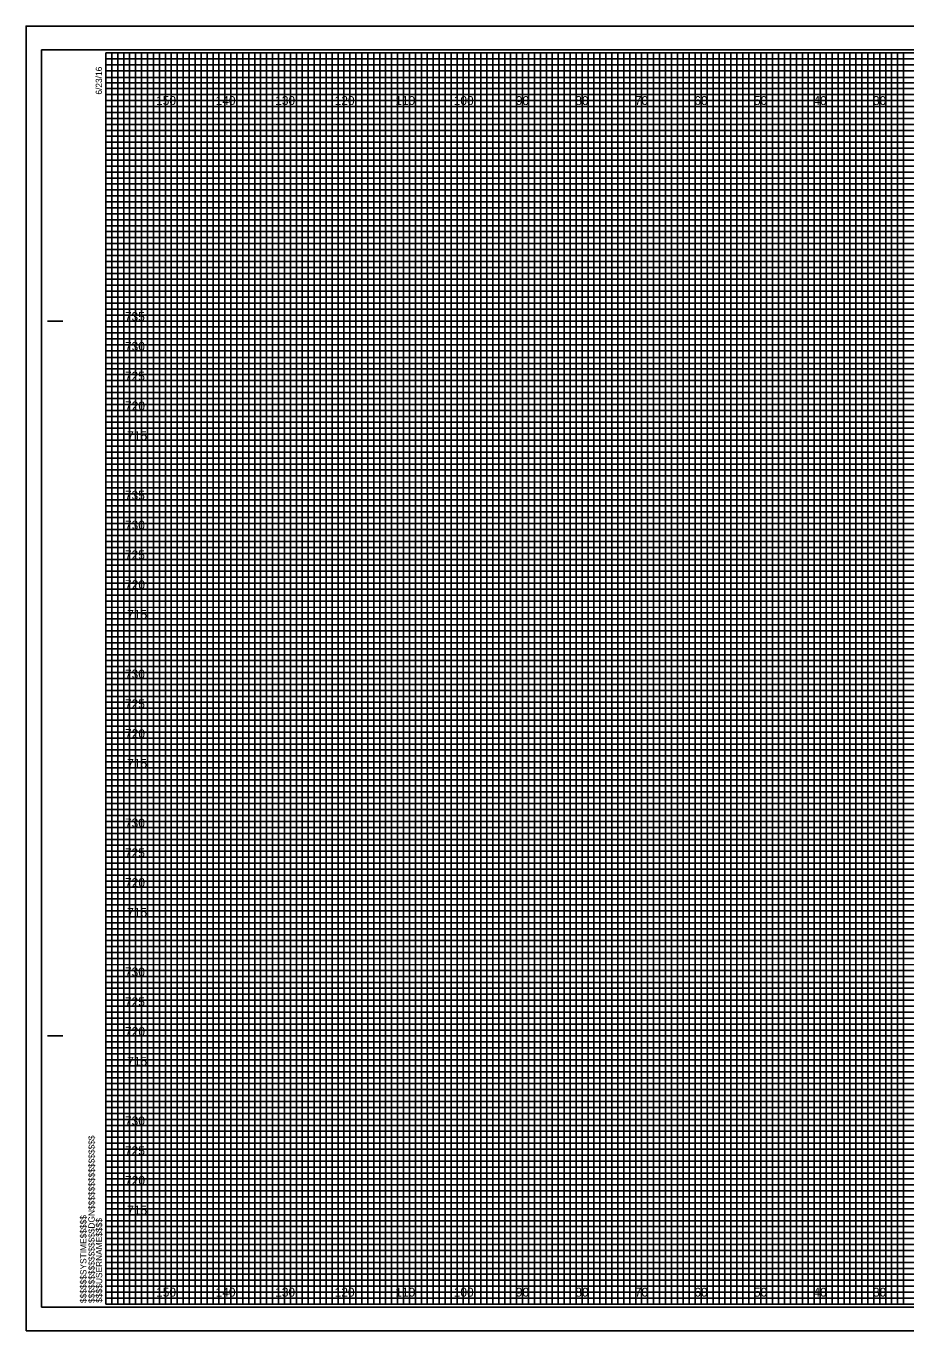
# Model space of a CAD drawing. Extents: x -13 to 323, y -5 to 434.
# Drawn here: x -13.4 to 134.4, y -4.5 to 214.5 of the extents above; entities that cross this region are included whole.
import ezdxf

# ---------------------------------------------------------------- set-up
doc = ezdxf.new("R2010")
doc.units = 0
for name, color, linetype in [('Prop XS Elevation Labels', 7, 'Continuous'), ('Prop XS Offset Labels', 7, 'Continuous'), ('Sheet Cross Section CELL', 7, 'Continuous'), ('Sheet Cross Section Grid Major CELL', 7, 'Continuous'), ('Sheet Cross Section Grid Middle CELL', 7, 'Continuous'), ('Sheet Cross Section Grid Minor 1 CELL', 7, 'Continuous'), ('Sheet Cross Section Grid Minor 2 CELL', 7, 'Continuous'), ('Sheet Cutting Line CELL', 7, 'Continuous'), ('Sheet DOT Grid CELL', 7, 'Continuous'), ('Sheet Plot Border Inside CELL', 7, 'Continuous'), ('Sheet Plot Border Outside CELL', 7, 'Continuous')]:
    doc.layers.add(name, color=color, linetype=linetype)

msp = doc.modelspace()

# ---------------------------------------------------------------- linework, layer by layer
at = {"layer": 'Sheet Cross Section CELL'}
for p, q in [((-9.8, 165), (-7.3, 165)), ((-9.7, 165), (-7.2, 165)), ((-9.8, 45), (-7.3, 45)), ((-9.7, 45), (-7.2, 45)), ((0, 0), (0, 0)), ((0, 0), (0, 0)), ((0, 0), (0, 0)), ((0, 0), (0, 0)), ((0, 0), (0, 0)), ((0, 0), (0, 0)), ((0, 0), (0, 0))]:
    msp.add_line(p, q, dxfattribs=at)
msp.add_lwpolyline([(320, 210), (0, 210), (0, 0), (320, 0)], close=True, dxfattribs=at)
at = {"layer": 'Sheet Cross Section Grid Major CELL'}
for p, q in [((10, 210), (0, 210)), ((10, 0), (10, 210)), ((30, 210), (20, 210)), ((20, 210), (20, 0)), ((30, 0), (30, 210)), ((50, 210), (40, 210)), ((40, 210), (40, 0)), ((50, 0), (50, 210)), ((70, 210), (60, 210)), ((60, 210), (60, 0)), ((70, 0), (70, 210)), ((90, 210), (80, 210)), ((80, 210), (80, 0)), ((90, 0), (90, 210)), ((110, 210), (100, 210)), ((100, 210), (100, 0)), ((110, 0), (110, 210)), ((130, 210), (120, 210)), ((120, 210), (120, 0)), ((130, 0), (130, 210)), ((20, 0), (10, 0)), ((40, 0), (30, 0)), ((60, 0), (50, 0)), ((80, 0), (70, 0)), ((100, 0), (90, 0)), ((120, 0), (110, 0)), ((140, 0), (130, 0))]:
    msp.add_line(p, q, dxfattribs=at)
for points in [[(0, 200), (320, 200), (320, 190), (0, 190)], [(0, 180), (320, 180), (320, 170), (0, 170)], [(0, 160), (320, 160), (320, 150), (0, 150)], [(0, 140), (320, 140), (320, 130), (0, 130)], [(0, 120), (320, 120), (320, 110), (0, 110)], [(0, 100), (320, 100), (320, 90), (0, 90)], [(0, 80), (320, 80), (320, 70), (0, 70)], [(0, 60), (320, 60), (320, 50), (0, 50)], [(0, 40), (320, 40), (320, 30), (0, 30)], [(0, 20), (320, 20), (320, 10), (0, 10)]]:
    msp.add_lwpolyline(points, dxfattribs=at)
at = {"layer": 'Sheet Cross Section Grid Middle CELL'}
for points in [[(0, 210), (5, 210), (5, 0), (15, 0), (15, 210), (25, 210), (25, 0), (35, 0), (35, 210), (45, 210), (45, 0), (55, 0), (55, 210), (65, 210), (65, 0), (75, 0), (75, 210), (85, 210), (85, 0), (95, 0), (95, 210), (105, 210), (105, 0), (115, 0), (115, 210), (125, 210), (125, 0), (135, 0)], [(0, 205), (275, 205)], [(0, 185), (320, 185), (320, 195), (0, 195)], [(0, 165), (320, 165), (320, 175), (0, 175)], [(0, 145), (320, 145), (320, 155), (0, 155)], [(0, 125), (320, 125), (320, 135), (0, 135)], [(0, 105), (320, 105), (320, 115), (0, 115)], [(0, 85), (320, 85), (320, 95), (0, 95)], [(0, 65), (320, 65), (320, 75), (0, 75)], [(0, 45), (320, 45), (320, 55), (0, 55)], [(0, 25), (320, 25), (320, 35), (0, 35)], [(0, 5), (320, 5), (320, 15), (0, 15)]]:
    msp.add_lwpolyline(points, dxfattribs=at)
at = {"layer": 'Sheet Cross Section Grid Minor 1 CELL'}
for p, q in [((0, 209), (260, 209)), ((260, 207.98), (0, 207.98)), ((0, 207.98), (0, 207)), ((0, 207), (260, 207)), ((260, 205.89), (0, 205.89)), ((0, 205.89), (0, 204)), ((0, 204), (320, 204))]:
    msp.add_line(p, q, dxfattribs=at)
for points in [[(0, 203), (270, 203), (320, 203), (320, 202), (0, 202)], [(0, 201), (320, 201), (320, 199), (0, 199)], [(0, 198), (320, 198), (320, 197), (0, 196.98)], [(0, 196), (320, 196), (320, 194), (0, 194)], [(0, 193), (320, 193), (320, 192), (0, 192)], [(0, 191), (320, 191), (320, 189), (0, 189)], [(0, 188), (320, 188), (320, 187), (0, 187)], [(0, 186), (320, 186), (320, 184), (0, 184)], [(0, 183), (320, 183), (320, 182), (0, 182)], [(0, 181), (320, 181), (320, 179), (0, 179)], [(0, 178), (320, 178), (320, 177), (0, 177)], [(0, 176), (320, 176), (320, 173.95), (320, 173), (320, 172), (0, 172)], [(0, 174), (320, 174), (320, 173), (0, 173)], [(0, 171), (320, 171), (320, 169), (0, 169.03)], [(0, 169.03), (320, 169), (320, 168), (0, 168)], [(0, 167), (320, 167), (320, 166), (0, 166)], [(0, 164), (320, 164), (320, 163), (0, 163)], [(0, 162), (320, 162), (320, 161), (0, 161)], [(-0.07, 158.89), (320, 158.89), (320, 157.88), (-0.07, 157.88)], [(0, 157), (320, 157), (320, 156), (0, 156)], [(0, 154), (320, 154), (320, 153), (0, 153)], [(0, 152), (320, 152), (320, 151), (0, 151)], [(0, 149), (320, 149), (320, 148), (0, 148)], [(0, 147), (320, 147), (320, 146), (0, 146)], [(0, 144), (320, 144), (320, 143), (0, 143)], [(0, 142), (320, 142), (320, 141), (0, 141)], [(0, 139), (320, 139), (319.99, 137.98), (0, 138)], [(0, 137), (320, 137), (320, 136), (0, 136)], [(0, 134), (320, 134), (320, 133), (0, 133)], [(0, 132), (320, 132), (320, 131), (0, 131)], [(0, 129), (320, 129), (320, 128), (0, 128)], [(0, 127), (320, 127), (320, 126), (0, 126)], [(0, 124), (320, 124), (320, 123), (0, 123)], [(0, 122), (320, 122), (320, 121), (0, 121)], [(0, 119), (320, 119), (320, 118), (0, 118)], [(0, 116.99), (320.07, 116.91), (320, 116), (0, 116)], [(0, 114), (320, 114), (320, 113), (0, 113)], [(0, 112), (320, 112), (320, 111), (0, 111)], [(0, 109), (320, 109), (320, 108), (0, 108)], [(0, 107), (320, 107), (320, 106), (0, 106)], [(0, 104), (320, 104), (320, 103), (0, 103)], [(0, 102), (320, 102), (320, 101), (0, 101)], [(0, 99), (320, 99), (320, 98), (0, 98)], [(0, 97), (320, 97), (320, 96), (0, 96)], [(0, 94), (320, 94), (320, 93), (0, 93)], [(0, 92), (320, 92), (320, 91), (0, 91)], [(0, 89), (320, 89), (320, 88), (0, 88)], [(0, 87), (320, 87), (320, 86), (0, 86)], [(0, 84), (320, 84), (320, 83), (0, 83)], [(0, 82), (320, 82), (320, 81), (0, 81)], [(0, 79), (320, 79), (319.99, 77.98), (0, 78)], [(0, 77), (320, 77), (320, 76), (0, 76)], [(0, 74), (320, 74), (320, 73), (0, 73)], [(0, 72), (320, 72), (320, 71), (0, 71)], [(0, 69), (320, 69), (320, 68), (0, 68)], [(0, 67), (320, 67), (320, 66), (0, 66)], [(0, 64), (320, 64), (320, 63), (0, 63)], [(0, 62), (320, 62), (320, 61), (0, 61)], [(0, 59), (320, 59), (320, 58), (0, 58)], [(0, 56.99), (320.07, 56.91), (320, 56), (0, 56)], [(0, 54), (320, 54), (320, 53), (0, 53)], [(0, 52), (320, 52), (320, 51), (0, 51)], [(0, 49), (320, 49), (320, 48), (0, 48)], [(0, 47), (320, 47), (320, 46), (0, 46)], [(0, 44), (320, 44), (320, 43), (0, 43)], [(0, 42), (320, 42), (320, 41), (0, 41)], [(0, 39), (320, 39), (320, 38), (0, 38)], [(0, 37), (320, 37), (320, 36), (0, 36)], [(0, 34), (320, 34), (320, 33), (0, 33)], [(0, 32), (320, 32), (320, 31), (0, 31)], [(0, 29), (320, 29), (320, 28), (0, 28)], [(0, 27), (320, 27), (320, 26), (0, 26)], [(0, 24), (320, 24), (320, 23), (0, 23)], [(0, 22), (320, 22), (320, 21), (0, 21)], [(0, 19), (320, 19), (320, 18), (0, 18)], [(0, 17), (320, 17), (320, 16), (0, 16)], [(0, 14), (320, 14), (320, 13), (0, 13)], [(0, 12), (320, 12), (320, 11), (0, 11)], [(0, 9), (320, 9), (320, 8), (0, 8)], [(0, 7), (320, 7), (320, 6), (0, 6)], [(0, 4), (320, 4), (320, 3), (0, 3)], [(0, 2), (320, 2), (320, 1), (0, 1)]]:
    msp.add_lwpolyline(points, dxfattribs=at)
at = {"layer": 'Sheet Cross Section Grid Minor 2 CELL'}
for points in [[(0, 0), (1, 0), (1, 210), (2, 210), (2, 0)], [(2, 0), (3, 0), (3, 210), (4, 210), (4, 0)], [(5, 0), (6, 0), (6, 210), (7, 210), (7, 0)], [(7, 0), (8, 0), (8, 210), (9, 210), (9, 0)], [(10, 0), (11, 0), (11, 210), (12, 210), (12, 0)], [(12, 0), (13, 0), (13, 210), (14, 210), (14, 0)], [(15, 0), (16, 0), (16, 210), (17, 210), (17, 0)], [(17, 0), (18, 0), (18, 210), (19, 210), (19, 0)], [(20, 0), (21, 0), (21, 210), (22, 210), (22, 0)], [(22, 0), (23, 0), (23, 210), (24, 210), (24, 0)], [(25, 0), (26, 0), (26, 210), (27, 210), (27, 0)], [(27, 0), (28, 0), (28, 210), (29, 210), (29, 0)], [(30, 0), (31, 0), (31, 210), (32, 210), (32, 0)], [(32, 0), (33, 0), (33, 210), (34, 210), (34, 0)], [(35, 0), (36, 0), (36, 210), (37, 210), (37, 0)], [(37, 0), (38, 0), (38, 210), (39, 210), (39, 0)], [(40, 0), (41, 0), (41, 210), (42, 210), (42, 0)], [(42, 0), (43, 0), (43, 210), (44, 210), (44, 0)], [(45, 0), (46, 0), (46, 210), (47, 210), (47, 0)], [(47, 0), (48, 0), (48, 210), (49, 210), (49, 0)], [(50, 0), (51, 0), (51, 210), (52, 210), (52, 0)], [(52, 0), (53, 0), (53, 210), (54, 210), (54, 0)], [(55, 0), (56, 0), (56, 210), (57, 210), (57, 0)], [(57, 0), (58, 0), (58, 210), (59, 210), (59, 0)], [(60, 0), (61, 0), (61, 210), (62, 210), (62, 0)], [(62, 0), (63, 0), (63, 210), (64, 210), (64, 0)], [(65, 0), (66, 0), (66, 210), (67, 210), (67, 0)], [(67, 0), (68, 0), (68, 210), (69, 210), (69, 0)], [(70, 0), (71, 0), (71, 210), (72, 210), (72, 0)], [(72, 0), (73, 0), (73, 210), (74, 210), (74, 0)], [(75, 0), (76, 0), (76, 210), (77, 210), (77, 0)], [(77, 0), (78, 0), (78, 210), (79, 210), (79, 0)], [(80, 0), (81, 0), (81, 210), (82, 210), (82, 0)], [(82, 0), (83, 0), (83, 210), (84, 210), (84, 0)], [(85, 0), (86, 0), (86, 210), (87, 210), (87, 0)], [(87, 0), (88, 0), (88, 210), (89, 210), (89, 0)], [(90, 0), (91, 0), (91, 210), (92, 210), (92, 0)], [(92, 0), (93, 0), (93, 210), (94, 210), (94, 0)], [(95, 0), (96, 0), (96, 210), (97, 210), (97, 0)], [(97, 0), (98, 0), (98, 210), (99, 210), (99, 0)], [(100, 0), (101, 0), (101, 210), (102, 210), (102, 0)], [(102, 0), (103, 0), (103, 210), (104, 210), (104, 0)], [(105, 0), (106, 0), (106, 210), (107, 210), (107, 0)], [(107, 0), (108, 0), (108, 210), (109, 210), (109, 0)], [(110, 0), (111, 0), (111, 210), (112, 210), (112, 0)], [(112, 0), (113, 0), (113, 210), (114, 210), (114, 0)], [(115, 0), (116, 0), (116, 210), (117, 210), (117, 0)], [(117, 0), (118, 0), (118, 210), (119, 210), (119, 0)], [(120, 0), (121, 0), (121, 210), (122, 210), (122, 0)], [(122, 0), (123, 0), (123, 210), (124, 210), (124, 0)], [(125, 0), (126, 0), (126, 210), (127, 210), (127, 0)], [(127, 0), (128, 0), (128, 210), (129, 210), (129, 0)], [(130, 0), (131, 0), (131, 210), (132, 210), (132, 0)], [(132, 0), (133, 0), (133, 210), (134, 210), (134, 0)]]:
    msp.add_lwpolyline(points, dxfattribs=at)
at = {"layer": 'Sheet Cutting Line CELL'}
for p, q in [((323.3, 214.5), (-13.4, 214.5)), ((-13.4, 214.5), (-13.4, -4.5)), ((-13.4, -4.5), (323.3, -4.5))]:
    msp.add_line(p, q, dxfattribs=at)
at = {"layer": 'Sheet DOT Grid CELL'}
for p, q in [((10, 0), (10, 210)), ((20, 0), (20, 210)), ((30, 0), (30, 210)), ((40, 0), (40, 210)), ((50, 0), (50, 210)), ((60, 0), (60, 210)), ((70, 0), (70, 210)), ((80, 0), (80, 210)), ((90, 0), (90, 210)), ((100, 0), (100, 210)), ((110, 0), (110, 210)), ((120, 0), (120, 210)), ((130, 0), (130, 210)), ((0, 200), (320, 200)), ((0, 190), (320, 190)), ((0, 180), (320, 180)), ((0, 170), (320, 170)), ((0, 160), (320, 160)), ((0, 150), (320, 150)), ((0, 140), (320, 140)), ((0, 130), (320, 130)), ((0, 120), (320, 120)), ((0, 110), (320, 110)), ((0, 100), (320, 100)), ((0, 90), (320, 90)), ((0, 80), (320, 80)), ((0, 70), (320, 70)), ((0, 60), (320, 60)), ((0, 50), (320, 50)), ((0, 40), (320, 40)), ((0, 30), (320, 30)), ((0, 20), (320, 20)), ((0, 10), (320, 10))]:
    msp.add_line(p, q, dxfattribs=at)
at = {"layer": 'Sheet Plot Border Inside CELL'}
msp.add_lwpolyline([(-10.8, -0.5), (322.4, -0.5), (322.4, 210.5), (-10.8, 210.5)], close=True, dxfattribs=at)
at = {"layer": 'Sheet Plot Border Outside CELL'}
msp.add_lwpolyline([(-13.4, -4.5), (323.3, -4.5), (323.3, 214.5), (-13.4, 214.5)], close=True, dxfattribs=at)

# ---------------------------------------------------------------- texts
at = {"layer": 'Prop XS Elevation Labels'}
for s, p in [('735', (3.2, 165)), ('730', (3.22, 160)), ('725', (3.21, 155)), ('720', (3.23, 150)), ('715', (3.59, 145)), ('735', (3.2, 135)), ('730', (3.22, 130)), ('725', (3.21, 125)), ('720', (3.23, 120)), ('715', (3.59, 115)), ('730', (3.22, 105)), ('725', (3.21, 100)), ('720', (3.23, 95)), ('715', (3.59, 90)), ('730', (3.22, 80)), ('725', (3.21, 75)), ('720', (3.23, 70)), ('715', (3.59, 65)), ('730', (3.22, 55)), ('725', (3.21, 50)), ('720', (3.23, 45)), ('715', (3.59, 40)), ('730', (3.22, 30)), ('725', (3.21, 25)), ('720', (3.23, 20)), ('715', (3.59, 15))]:
    msp.add_text(s, height=1.5, dxfattribs=at).set_placement(p)
at = {"layer": 'Prop XS Offset Labels'}
for s, p in [('150', (8.44, 201.25)), ('140', (18.44, 201.25)), ('130', (28.44, 201.25)), ('120', (38.44, 201.25)), ('110', (48.62, 201.25)), ('100', (58.44, 201.25)), ('90', (68.86, 201.25)), ('80', (78.86, 201.25)), ('70', (88.86, 201.25)), ('60', (98.86, 201.25)), ('50', (108.86, 201.25)), ('40', (118.86, 201.25)), ('30', (128.86, 201.25)), ('150', (8.44, 1.25)), ('140', (18.44, 1.25)), ('130', (28.44, 1.25)), ('120', (38.44, 1.25)), ('110', (48.62, 1.25)), ('100', (58.44, 1.25)), ('90', (68.86, 1.25)), ('80', (78.86, 1.25)), ('70', (88.86, 1.25)), ('60', (98.86, 1.25)), ('50', (108.86, 1.25)), ('40', (118.86, 1.25)), ('30', (128.86, 1.25))]:
    msp.add_text(s, height=1.5, dxfattribs=at).set_placement(p)
at = {"layer": 'Sheet Cross Section CELL'}
for s, p in [('6/23/16', (-0.65, 203)), ('$$$$$$$$$$$$$$$$DGN$$$$$$$$$$$$$$$$', (-1.88, 0.18)), ('$$$$$$SYSTIME$$$$$', (-3.26, 0.18)), ('$$$$USERNAME$$$$', (-0.62, 0.23))]:
    msp.add_text(s, height=1.05, rotation=90, dxfattribs=at).set_placement(p)

doc.saveas('drawing.dxf')
